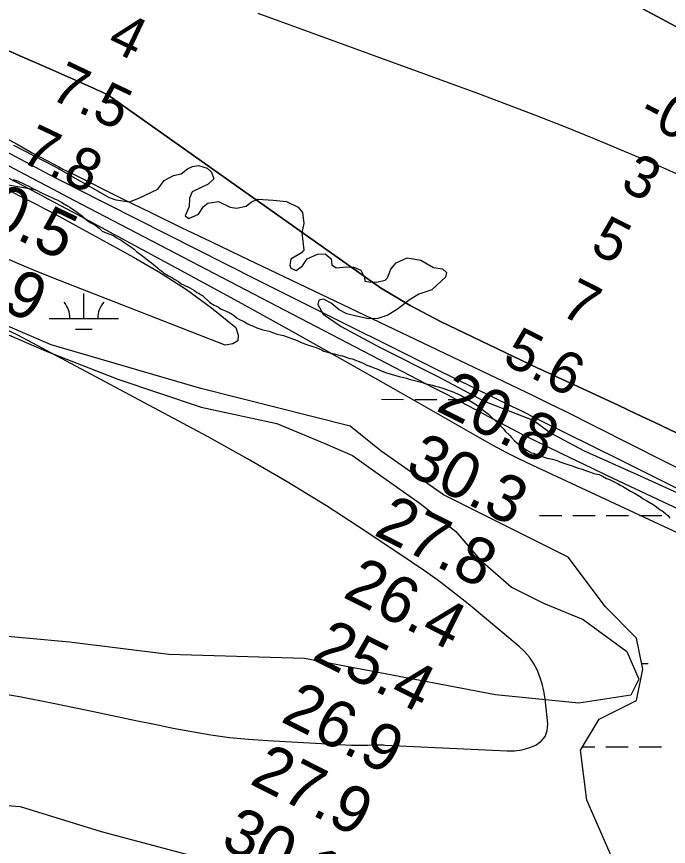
# Model space of a CAD drawing. Extents: x 3219052 to 3256913, y 800770 to 826146.
# Drawn here: x 3237159 to 3238098, y 813264 to 814457 of the extents above; entities that cross this region are included whole.
import ezdxf

# ---------------------------------------------------------------- set-up
doc = ezdxf.new("R2010")
doc.units = 0
for name, color, linetype in [('V-RIVR-EDGE', 7, 'Continuous'), ('V-RIVR-RANG', 7, 'Continuous'), ('V-SITE-VEGE', 7, 'Continuous'), ('V-TOPO-DPTH', 7, 'Continuous'), ('V-TOPO-MAJR', 7, 'Continuous'), ('V-TOPO-MINR', 7, 'Continuous'), ('V-TOPO-SHOR', 7, 'Continuous'), ('V-TOPO-WATR', 7, 'Continuous'), ('V-WETL-SWMP', 7, 'Continuous')]:
    doc.layers.add(name, color=color, linetype=linetype)

msp = doc.modelspace()

# ---------------------------------------------------------------- linework, layer by layer
at = {"layer": 'V-RIVR-EDGE'}
for points in [[(3237155.1, 814272.4), (3237213.5, 814242.2), (3237292.4, 814197), (3237302.3, 814193.8), (3237321.7, 814190.6), (3237335.5, 814196.1), (3237362.5, 814209), (3237371.6, 814221.3), (3237385, 814228.8), (3237396.1, 814231.1), (3237405.2, 814238.2), (3237412.3, 814241.7), (3237421, 814242.9), (3237433.7, 814239.3), (3237440, 814233.4), (3237443.1, 814223.9), (3237435.2, 814216), (3237411.9, 814205), (3237408.3, 814195.9), (3237407.9, 814184), (3237401.9, 814170.6), (3237407.4, 814167), (3237421.3, 814172.9), (3237428.4, 814184), (3237434.4, 814188.7), (3237449.8, 814191.4), (3237466.8, 814183.1), (3237475.8, 814181.9), (3237489.7, 814184.6), (3237497.2, 814190.9), (3237506.7, 814194.8), (3237528.5, 814193.2), (3237547.8, 814191.2), (3237564.4, 814183.2), (3237570.7, 814175.3), (3237573, 814159.5), (3237569.8, 814146.1), (3237572.6, 814121.5), (3237569.4, 814117.2), (3237553.9, 814108.5), (3237552.7, 814099.9), (3237553.9, 814095.5), (3237561.8, 814091.9), (3237570.9, 814098.6), (3237577.7, 814108.9), (3237592.3, 814115.6), (3237603.4, 814115.9), (3237612.1, 814108.8), (3237613.2, 814100.1), (3237619.5, 814096.1), (3237634.6, 814097.3), (3237644.8, 814096.9), (3237654.7, 814092.5), (3237660.2, 814081.8), (3237660.6, 814076.7), (3237666.5, 814075.5), (3237678, 814075.4), (3237689.9, 814078.2), (3237693.4, 814081.7), (3237697.8, 814094), (3237705.7, 814103), (3237721.6, 814110.1), (3237741.3, 814106.9), (3237759.5, 814096.2), (3237772.5, 814094.2), (3237778, 814089), (3237776.8, 814082.3), (3237757, 814064.2), (3237738.4, 814057.9), (3237724.2, 814049.2), (3237707.5, 814036.2), (3237693.7, 814028), (3237679.4, 814023.2), (3237666, 814022.5), (3237650.6, 814025.7), (3237634.8, 814029.7), (3237623.7, 814035.6), (3237611.9, 814045.2), (3237601.2, 814050.7), (3237594.5, 814049.5), (3237592.9, 814043.2), (3237600.8, 814029.4), (3237626.4, 814011.5), (3237682.5, 813981.3), (3237765.4, 813939.6)], [(3237765.4, 813939.6), (3237832.1, 813904.3), (3237904, 813876.4), (3237927.7, 813858.6), (3237975.5, 813833.1), (3238052.5, 813798.6), (3238167.8, 813746.5), (3238286.2, 813679), (3238474.2, 813593.9)]]:
    msp.add_lwpolyline(points, dxfattribs=at)
at = {"layer": 'V-SITE-VEGE'}
for points in [[(3237154.4, 814222.7), (3237161.5, 814220.5), (3237177.8, 814212.7), (3237184.5, 814209), (3237189.8, 814206.8), (3237193.1, 814204.9), (3237196, 814203.1), (3237209, 814197.6), (3237214.7, 814194.4), (3237217.6, 814193.5), (3237224.3, 814189.9), (3237232.5, 814184.8), (3237235.8, 814183), (3237245, 814177), (3237254.1, 814170), (3237257, 814167.2), (3237265.2, 814161.2), (3237271.9, 814157.5), (3237278.2, 814152.9), (3237282.5, 814148.7), (3237285.9, 814147.3), (3237292.1, 814144.6), (3237298.8, 814142.4), (3237302.6, 814139.6), (3237306, 814137.8), (3237309.9, 814135.5), (3237312.3, 814133.6), (3237319.5, 814129), (3237323.3, 814126.7), (3237325.7, 814124.4), (3237328.6, 814122.5), (3237332, 814119.3), (3237341.1, 814112.8), (3237350.3, 814105.4), (3237353.7, 814103.1), (3237359, 814098.9), (3237365.7, 814092.8), (3237368.6, 814091), (3237371, 814088.7), (3237377.8, 814084.5), (3237383, 814081.8), (3237386.9, 814079), (3237392.2, 814076.2), (3237396, 814073), (3237399.4, 814071.2), (3237402.3, 814069.8), (3237405.6, 814068.4), (3237408.5, 814067.1), (3237415.2, 814063.4), (3237418.6, 814060.6)], [(3237418.6, 814060.6), (3237421.5, 814059.2), (3237423.9, 814057.4), (3237426.7, 814056), (3237437.4, 814045.8), (3237443.6, 814042.1), (3237447, 814040.7), (3237449.9, 814039.4), (3237453.7, 814036.6), (3237457.5, 814035.2), (3237465.2, 814031.6), (3237471, 814028.4), (3237476.7, 814023.7), (3237480.1, 814021.4), (3237484.4, 814019.6), (3237487.3, 814018.2), (3237492.1, 814015.5), (3237495.9, 814013.6), (3237498.8, 814012.3), (3237505, 814009.5), (3237513.6, 814006.9), (3237522.7, 814004.7), (3237528.9, 814002.4), (3237534.6, 814000.6), (3237538.9, 813999.7), (3237543.7, 813998.4), (3237563.3, 813991.2), (3237568.1, 813988.9), (3237576.7, 813985.7), (3237584.3, 813983), (3237587.2, 813982.1), (3237590.5, 813981.3), (3237599.2, 813977.6), (3237601.6, 813975.8), (3237605.4, 813974.9), (3237610.2, 813973.6), (3237618.3, 813971.8), (3237625, 813969.6), (3237628.3, 813969.2), (3237631.2, 813968.3), (3237634.5, 813966.9), (3237638.8, 813965.6), (3237642.1, 813965.1), (3237657, 813959.3), (3237662.7, 813956.5), (3237680.4, 813949.7), (3237684.2, 813947.9), (3237691.9, 813944.7), (3237703.4, 813941.6), (3237710, 813939.4), (3237720.5, 813937.2), (3237724.4, 813935.8), (3237743.4, 813931), (3237746.8, 813929.6), (3237753.5, 813927.9), (3237757.8, 813927), (3237762.1, 813925.6), (3237766.4, 813924.8), (3237774.5, 813922.1), (3237782.1, 813919.4), (3237786.4, 813918), (3237789.8, 813916.7), (3237799.4, 813912.1), (3237805.1, 813908.9), (3237813.8, 813903.4), (3237821.5, 813898.8), (3237833, 813889.5), (3237838.3, 813885.8), (3237840.7, 813883.5), (3237843.2, 813880.7), (3237848, 813876.5), (3237850.9, 813874.2), (3237858.2, 813866.2), (3237860.6, 813863.9), (3237862.5, 813861.1), (3237869.3, 813854.6), (3237871.7, 813851.8), (3237876.1, 813847.1), (3237881.9, 813842.5), (3237885.7, 813838.7), (3237889.6, 813836.4), (3237893.9, 813833.7), (3237900.2, 813830), (3237904, 813829.1), (3237909.7, 813826.4), (3237915.9, 813824.6), (3237923.1, 813822.3), (3237930.7, 813820.6), (3237934.1, 813819.7), (3237938.4, 813818.4), (3237941.2, 813817), (3237949.8, 813813.8), (3237960.3, 813810.7), (3237966.1, 813808.4), (3237973.3, 813806.2), (3237979.5, 813803.9), (3237985.2, 813802.2), (3237990, 813800.3), (3237997.6, 813798.6), (3238002.4, 813796.3), (3238008.6, 813793.1)], [(3237979.9, 813330.2), (3237971, 813402), (3237997.9, 813446.8), (3238051.6, 813473.7), (3238060.6, 813518.5), (3238051.6, 813563.4), (3238006.8, 813608.2), (3237953.1, 813680), (3237773.8, 813769.6), (3237684.2, 813832.4), (3237639.4, 813868.3), (3237424.4, 813922.1), (3237209.3, 813984.9), (3237146.6, 814011.8)], [(3238008.6, 813793.1), (3238012.9, 813791.3), (3238024.4, 813785.8), (3238028.8, 813783), (3238031.6, 813781.7), (3238042.7, 813774.8), (3238048.9, 813771.6), (3238058.1, 813766), (3238061.4, 813763.7), (3238066.2, 813761), (3238075.4, 813755.4), (3238080.2, 813752.2), (3238085.5, 813748), (3238088.4, 813746.2), (3238093.2, 813742.5), (3238096.5, 813739.7), (3238099.5, 813736)], [(3235757.7, 813581.3), (3235856.3, 813554.4), (3235945.9, 813473.7), (3235990.7, 813419.9), (3236026.5, 813393), (3236143, 813357.1), (3236232.6, 813330.2), (3236367, 813321.3), (3236483.5, 813303.3), (3236626.9, 813312.3), (3236797.1, 813321.3), (3236886.7, 813330.2), (3237048, 813330.2), (3237164.5, 813321.3), (3237281, 813285.4), (3237549.8, 813213.6), (3237693.2, 813168.8), (3237791.8, 813132.9), (3237899.3, 813115), (3237971, 813168.8), (3238033.7, 813204.7), (3238015.8, 813249.5), (3237979.9, 813330.2)]]:
    msp.add_lwpolyline(points, dxfattribs=at)
at = {"layer": 'V-TOPO-DPTH'}
for points in [[(3238705.8, 814111.8), (3238307.8, 814332.8), (3238282.5, 814346.8), (3238257.2, 814360.9), (3238231.9, 814375), (3238206.6, 814389), (3238167.8, 814410.6), (3238161.8, 814413.9), (3238155.9, 814417.2), (3238150, 814420.4), (3238144, 814423.6), (3237988.9, 814507.3)], [(3237988.9, 814507.3), (3238144, 814423.6), (3238150, 814420.4), (3238155.9, 814417.2), (3238161.8, 814413.9), (3238167.8, 814410.6), (3238206.6, 814389), (3238231.9, 814375), (3238257.2, 814360.9), (3238282.5, 814346.8), (3238307.8, 814332.8), (3238705.8, 814111.8)], [(3238473.6, 813684.6), (3238077.1, 813873.7), (3238051.2, 813886), (3238025.2, 813898.2), (3237999.3, 813910.3), (3237973.2, 813922.4), (3237932.6, 813941.1), (3237926.9, 813943.7), (3237921.1, 813946.4), (3237915.4, 813949.1), (3237909.7, 813951.8), (3237769.7, 814018.7), (3237725.6, 814041.9), (3237683, 814067.3), (3237289.3, 814345.4), (3237284.5, 814347.6), (3237279.7, 814349.8), (3237274.9, 814352), (3237270, 814354.2), (3237202.7, 814383.9), (3237164.2, 814400.9), (3237125.8, 814418.1)], [(3238473.6, 813684.6), (3238077.1, 813873.7), (3238051.2, 813886), (3238025.2, 813898.2), (3237999.3, 813910.3), (3237973.2, 813922.4), (3237932.6, 813941.1), (3237926.9, 813943.7), (3237921.1, 813946.4), (3237915.4, 813949.1), (3237909.7, 813951.8), (3237769.7, 814018.7), (3237725.6, 814041.9), (3237683, 814067.3), (3237289.3, 814345.4), (3237284.5, 814347.6), (3237279.7, 814349.8), (3237274.9, 814352), (3237270, 814354.2), (3237202.7, 814383.9), (3237164.2, 814400.9), (3237125.8, 814418.1)], [(3237122.5, 814274.8), (3237192.8, 814237.3), (3237206, 814230.3), (3237219.2, 814223.4), (3237232.4, 814216.6), (3237245.7, 814209.8), (3237504.6, 814079.3), (3237568.9, 814046.9), (3237633.3, 814014.7), (3237697.8, 813982.7), (3237762.4, 813950.8), (3237872.5, 813896.6), (3237882.1, 813891.9), (3237891.6, 813887.2), (3237901.1, 813882.5), (3237910.7, 813877.7), (3238028, 813819.6), (3238096.2, 813785.9), (3238164.5, 813752.3)]]:
    msp.add_lwpolyline(points, dxfattribs=at)
at = {"layer": 'V-TOPO-MAJR'}
msp.add_lwpolyline([(3236663.1, 814452.7), (3237177.8, 814192.2), (3237188.4, 814186.8), (3237199, 814181.3), (3237209.6, 814175.7), (3237220.1, 814170), (3237327.8, 814111.3), (3237366.3, 814088.6), (3237403.8, 814064.5), (3237439.8, 814038.1), (3237474.7, 814010.1), (3237478.4, 813999.2), (3237477.8, 813990.8), (3237470.7, 813986.4), (3237459.3, 813984.5), (3237221.3, 814077.5), (3237191.1, 814089.6), (3237161.1, 814102.1), (3237131.2, 814115)], dxfattribs=at)
at = {"layer": 'V-TOPO-MINR'}
for points in [[(3237988.9, 814507.3), (3238144, 814423.6), (3238150, 814420.4), (3238155.9, 814417.2), (3238161.8, 814413.9), (3238167.8, 814410.6), (3238206.6, 814389), (3238231.9, 814375), (3238257.2, 814360.9), (3238282.5, 814346.8), (3238307.8, 814332.8), (3238705.8, 814111.8)], [(3237506.4, 814461.9), (3237822.7, 814347), (3237864.5, 814331.4), (3237906.3, 814315.5), (3237947.8, 814299.1), (3237989.1, 814282.3), (3238048.9, 814257.5), (3238060.2, 814252.7), (3238071.5, 814247.9), (3238082.8, 814243), (3238094, 814238), (3238653.9, 813984.9)], [(3236898.7, 814353.7), (3237171.1, 814212.7), (3237188.3, 814203.8), (3237205.5, 814194.8), (3237222.6, 814185.7), (3237239.6, 814176.5), (3237406.6, 814086.5), (3237483.3, 814044.7), (3237559.7, 814002.6), (3237635.8, 813959.9), (3237711.7, 813916.8), (3237826, 813851.2), (3237844.7, 813840.8), (3237863.5, 813830.8), (3237882.5, 813821.2), (3237901.8, 813811.9), (3238111.1, 813714.6)], [(3237057.7, 814290.3), (3237171.6, 814230.2), (3237191.9, 814219.5), (3237212.2, 814208.8), (3237232.5, 814198.2), (3237252.9, 814187.6), (3237759, 813923.9), (3237779, 813913.5), (3237798.9, 813903.1), (3237818.8, 813892.6), (3237838.7, 813882), (3237871.4, 813864.7), (3237874.9, 813862.8), (3237878.5, 813861), (3237882.1, 813859.1), (3237885.8, 813857.3), (3237922, 813839.5), (3237943.8, 813828.8), (3237965.7, 813818.2), (3237987.6, 813807.8), (3238009.5, 813797.4), (3238440.4, 813594.9)], [(3237138.2, 814285.8), (3237160, 814273.5), (3237181.9, 814261.4), (3237214.1, 814244.3), (3237220.1, 814241.1), (3237226.1, 814237.9), (3237232.2, 814234.8), (3237238.3, 814231.8), (3237311, 814195.8), (3237353.5, 814174.9), (3237396.1, 814154.1), (3237438.7, 814133.6), (3237481.5, 814113.1), (3237859.7, 813933.1), (3237881.8, 813922.5), (3237903.9, 813911.8), (3237925.8, 813900.9), (3237947.8, 813890), (3238467.6, 813628)], [(3237122.5, 814274.8), (3237192.8, 814237.3), (3237206, 814230.3), (3237219.2, 814223.4), (3237232.4, 814216.6), (3237245.7, 814209.8), (3237504.6, 814079.3), (3237568.9, 814046.9), (3237633.3, 814014.7), (3237697.8, 813982.7), (3237762.4, 813950.8), (3237872.5, 813896.6), (3237882.1, 813891.9), (3237891.6, 813887.2), (3237901.1, 813882.5), (3237910.7, 813877.7), (3238028, 813819.6), (3238096.2, 813785.9), (3238164.5, 813752.3)], [(3237466, 813420.6), (3237493.2, 813417.9), (3237520.6, 813415.9), (3237641.2, 813409.6), (3237647.2, 813409.4), (3237653.1, 813409.3), (3237659.1, 813409.3), (3237665.1, 813409.4), (3237672.8, 813409.7), (3237677, 813409.8), (3237681.3, 813409.8), (3237685.5, 813409.7), (3237687.6, 813409.7), (3237689.8, 813409.6), (3237865, 813401.2), (3237875.8, 813401.4), (3237886.3, 813402.7), (3237896.5, 813405.5), (3237906.5, 813409.3), (3237914.4, 813415.1), (3237920.2, 813422), (3237923, 813430.5), (3237923.9, 813440.2), (3237920, 813476.2), (3237918.3, 813486.9), (3237916, 813497.4), (3237912.6, 813507.6), (3237908.5, 813517.7), (3237903.3, 813527.1), (3237897.4, 813536), (3237890.3, 813544), (3237882.5, 813551.4), (3237809.1, 813612.5), (3237789.6, 813628.2), (3237769.8, 813643.4), (3237749.5, 813658.1), (3237728.9, 813672.3), (3237660.6, 813717.8), (3237605.2, 813753.6), (3237549, 813788.3), (3237491.9, 813821.3), (3237434.1, 813853.2), (3237161, 813998.8), (3237141.2, 814008.8)], [(3237114.5, 813487.5), (3237163.4, 813479.2), (3237212.2, 813469.9), (3237260.8, 813459.9), (3237304.1, 813450.6), (3237330.9, 813444.9), (3237357.8, 813439.4), (3237384.8, 813434), (3237411.8, 813428.9), (3237438.8, 813424.3), (3237466, 813420.6)]]:
    msp.add_lwpolyline(points, dxfattribs=at)
at = {"layer": 'V-TOPO-SHOR'}
msp.add_lwpolyline([(3237121.6, 814010.6), (3237201.8, 813976), (3237304.9, 813935.7), (3237425.2, 813895.3), (3237534, 813872.1), (3237602.8, 813843.3), (3237642.9, 813826), (3237682.9, 813797.3), (3237740.2, 813757), (3237791.7, 813716.8), (3237826, 813676.6), (3237871.7, 813636.4), (3237917.5, 813613.4), (3237974.8, 813590.3), (3238037.8, 813544.3), (3238054.9, 813504.2), (3238043.4, 813481.3), (3237968.8, 813470), (3237848.5, 813481.7), (3237573.5, 813533.9), (3237378.6, 813540), (3237235.3, 813557.5), (3237109.2, 813569.2)], dxfattribs=at)
at = {"layer": 'V-TOPO-WATR'}
msp.add_lwpolyline([(3237125.8, 814418.1), (3237164.2, 814400.9), (3237202.7, 814383.9), (3237270, 814354.2), (3237274.9, 814352), (3237279.7, 814349.8), (3237284.5, 814347.6), (3237289.3, 814345.4), (3237683, 814067.3), (3237725.6, 814041.9), (3237769.7, 814018.7), (3237909.7, 813951.8), (3237915.4, 813949.1), (3237921.1, 813946.4), (3237926.9, 813943.7), (3237932.6, 813941.1), (3237973.2, 813922.4), (3237999.3, 813910.3), (3238025.2, 813898.2), (3238051.2, 813886), (3238077.1, 813873.7), (3238473.6, 813684.6)], dxfattribs=at)
at = {"layer": 'V-WETL-SWMP'}
for p, q in [((3237256.1, 814023.1), (3237256.2, 814059.1)), ((3237206.1, 814023.2), (3237306.1, 814023)), ((3237244.1, 814007.7), (3237268.1, 814007.7)), ((3237684.4, 813906.8), (3237716.4, 813906.7)), ((3237732.4, 813906.7), (3237764.4, 813906.6)), ((3237780.4, 813906.6), (3237808.8, 813906.6)), ((3237912.1, 813739.8), (3237944.1, 813739.8)), ((3237960.1, 813739.7), (3237992.1, 813739.7)), ((3238008.1, 813739.6), (3238040.1, 813739.6)), ((3238056.1, 813739.5), (3238088.1, 813739.5)), ((3238058.9, 813526.9), (3238068.5, 813526.9)), ((3237974, 813407), (3237991.4, 813407)), ((3238007.4, 813407), (3238039.4, 813406.9)), ((3238055.4, 813406.9), (3238087.4, 813406.8))]:
    msp.add_line(p, q, dxfattribs=at)
for points in [[(3236901.4, 814257.4), (3237186.3, 814208.3), (3237189.8, 814206.8), (3237193.1, 814204.9), (3237196, 814203.1), (3237209, 814197.6), (3237214.7, 814194.4), (3237217.6, 814193.5), (3237224.3, 814189.9), (3237232.5, 814184.8), (3237235.8, 814183), (3237245, 814177), (3237254.1, 814170), (3237257, 814167.2), (3237265.2, 814161.2), (3237271.9, 814157.5), (3237278.2, 814152.9), (3237282.5, 814148.7), (3237285.9, 814147.3), (3237292.1, 814144.6), (3237298.8, 814142.4), (3237302.6, 814139.6), (3237306, 814137.8), (3237309.9, 814135.5), (3237312.3, 814133.6), (3237319.5, 814129), (3237323.3, 814126.7), (3237325.7, 814124.4)], [(3237325.7, 814124.4), (3237328.6, 814122.5), (3237332, 814119.3), (3237341.1, 814112.8), (3237350.3, 814105.4), (3237353.7, 814103.1), (3237359, 814098.9), (3237365.7, 814092.8), (3237368.6, 814091), (3237371, 814088.7), (3237377.8, 814084.5), (3237383, 814081.8), (3237386.9, 814079), (3237392.2, 814076.2), (3237396, 814073), (3237399.4, 814071.2), (3237402.3, 814069.8), (3237405.6, 814068.4), (3237408.5, 814067.1), (3237415.2, 814063.4), (3237418.6, 814060.6), (3237421.5, 814059.2), (3237423.9, 814057.4), (3237426.7, 814056), (3237437.4, 814045.8), (3237443.6, 814042.1), (3237447, 814040.7), (3237449.8, 814039.4), (3237453.7, 814036.6), (3237457.5, 814035.2), (3237465.2, 814031.6), (3237471, 814028.4), (3237476.7, 814023.7), (3237480.1, 814021.4), (3237484.4, 814019.6), (3237487.3, 814018.2), (3237492.1, 814015.5), (3237495.9, 814013.6), (3237498.8, 814012.3), (3237505, 814009.5), (3237513.6, 814006.9), (3237522.7, 814004.7), (3237528.9, 814002.4), (3237534.6, 814000.6), (3237538.9, 813999.7), (3237543.7, 813998.4), (3237563.3, 813991.2), (3237568.1, 813988.9), (3237576.7, 813985.7), (3237584.3, 813983), (3237587.2, 813982.1), (3237590.5, 813981.3), (3237599.2, 813977.6), (3237601.6, 813975.8), (3237605.4, 813974.9), (3237610.2, 813973.6), (3237618.3, 813971.8), (3237625, 813969.6), (3237628.3, 813969.2), (3237631.2, 813968.3), (3237634.5, 813966.9), (3237638.8, 813965.6), (3237642.1, 813965.1), (3237657, 813959.3), (3237662.7, 813956.5), (3237680.4, 813949.7), (3237684.2, 813947.9), (3237691.9, 813944.7), (3237703.4, 813941.6), (3237710, 813939.4), (3237720.5, 813937.2), (3237724.4, 813935.8), (3237743.4, 813931), (3237746.8, 813929.6), (3237753.5, 813927.9), (3237757.8, 813927), (3237762.1, 813925.6), (3237766.4, 813924.8), (3237774.5, 813922.1), (3237782.1, 813919.4), (3237786.4, 813918), (3237789.8, 813916.7), (3237799.4, 813912.1), (3237805.1, 813908.9), (3237813.8, 813903.4), (3237821.5, 813898.8), (3237833, 813889.5), (3237838.3, 813885.8), (3237840.7, 813883.5), (3237843.2, 813880.7), (3237848, 813876.5), (3237850.9, 813874.2), (3237858.2, 813866.2), (3237860.6, 813863.9), (3237862.5, 813861.1), (3237869.3, 813854.6), (3237871.7, 813851.8), (3237876.1, 813847.1), (3237881.9, 813842.5), (3237885.7, 813838.7), (3237889.6, 813836.4)], [(3237048, 813330.2), (3237164.5, 813321.3), (3237281, 813285.4), (3237549.8, 813213.6), (3237693.2, 813168.8), (3237791.8, 813132.9), (3237899.3, 813115), (3237971, 813168.8), (3238033.7, 813204.7), (3238015.8, 813249.5), (3237979.9, 813330.2), (3237971, 813402), (3237997.9, 813446.8), (3238051.6, 813473.7), (3238060.6, 813518.5), (3238051.6, 813563.4), (3238006.8, 813608.2), (3237953.1, 813680), (3237773.8, 813769.6), (3237684.2, 813832.4), (3237639.4, 813868.3), (3237424.4, 813922.1), (3237209.3, 813984.9), (3237146.6, 814011.8)], [(3237889.6, 813836.4), (3237893.9, 813833.7), (3237900.2, 813830), (3237904, 813829.1), (3237909.7, 813826.4), (3237915.9, 813824.6), (3237923.1, 813822.3), (3237930.7, 813820.6), (3237934.1, 813819.7), (3237938.4, 813818.4), (3237941.2, 813817), (3237949.8, 813813.8), (3237960.3, 813810.7), (3237966.1, 813808.4), (3237973.3, 813806.2), (3237979.5, 813803.9), (3237985.2, 813802.2), (3237990, 813800.3), (3237997.6, 813798.6), (3238002.4, 813796.3), (3238008.6, 813793.1), (3238012.9, 813791.3), (3238024.4, 813785.8), (3238028.8, 813783), (3238031.6, 813781.7), (3238042.7, 813774.8), (3238048.9, 813771.6), (3238058.1, 813766), (3238061.4, 813763.7), (3238066.2, 813761), (3238075.4, 813755.4), (3238080.2, 813752.2), (3238085.5, 813748), (3238088.4, 813746.2), (3238093.2, 813742.5), (3238096.5, 813739.7), (3238099.5, 813736)]]:
    msp.add_lwpolyline(points, dxfattribs=at)
for centre, start, end in [((3237200.9, 814023.7), 359.1081, 40.6518), ((3237311.4, 814023.5), 139.1081, 180.6517)]:
    msp.add_arc(centre, 35.2, start, end, dxfattribs=at)

# ---------------------------------------------------------------- texts
at = {"layer": 'V-RIVR-RANG'}
for s, height, rotation, p in [('4', 60, 334.5607, (3237287.1, 814412.2)), ('7.5', 60, 334.5607, (3237204.9, 814340.5)), ('-0', 60, 333.0512, (3238051.7, 814309.2)), ('7.8', 60, 334.5607, (3237162.6, 814249.9)), ('3', 60, 333.0512, (3238026.2, 814210)), ('40.5', 67, 334.2783, (3237067.3, 814181.3)), ('5', 60, 333.0512, (3237982.8, 814119.8)), ('27.9', 67, 334.2783, (3237023.9, 814091.2)), ('7', 60, 333.0512, (3237939.5, 814029.7)), ('5.6', 60, 333.0512, (3237856.5, 813959.7)), ('20.8', 67, 333.3483, (3237761, 813891.5)), ('30.3', 67, 333.3483, (3237716.4, 813802)), ('27.8', 67, 333.3483, (3237671.7, 813712.5)), ('26.4', 67, 333.3483, (3237627.1, 813623)), ('25.4', 67, 333.3483, (3237582.5, 813533.5)), ('26.9', 67, 333.3483, (3237537.6, 813444.1)), ('27.9', 67, 333.3483, (3237493, 813354.6)), ('30.1', 67, 333.3483, (3237450.7, 813264))]:
    msp.add_text(s, height=height, rotation=rotation, dxfattribs=at).set_placement(p)

doc.saveas('drawing.dxf')
